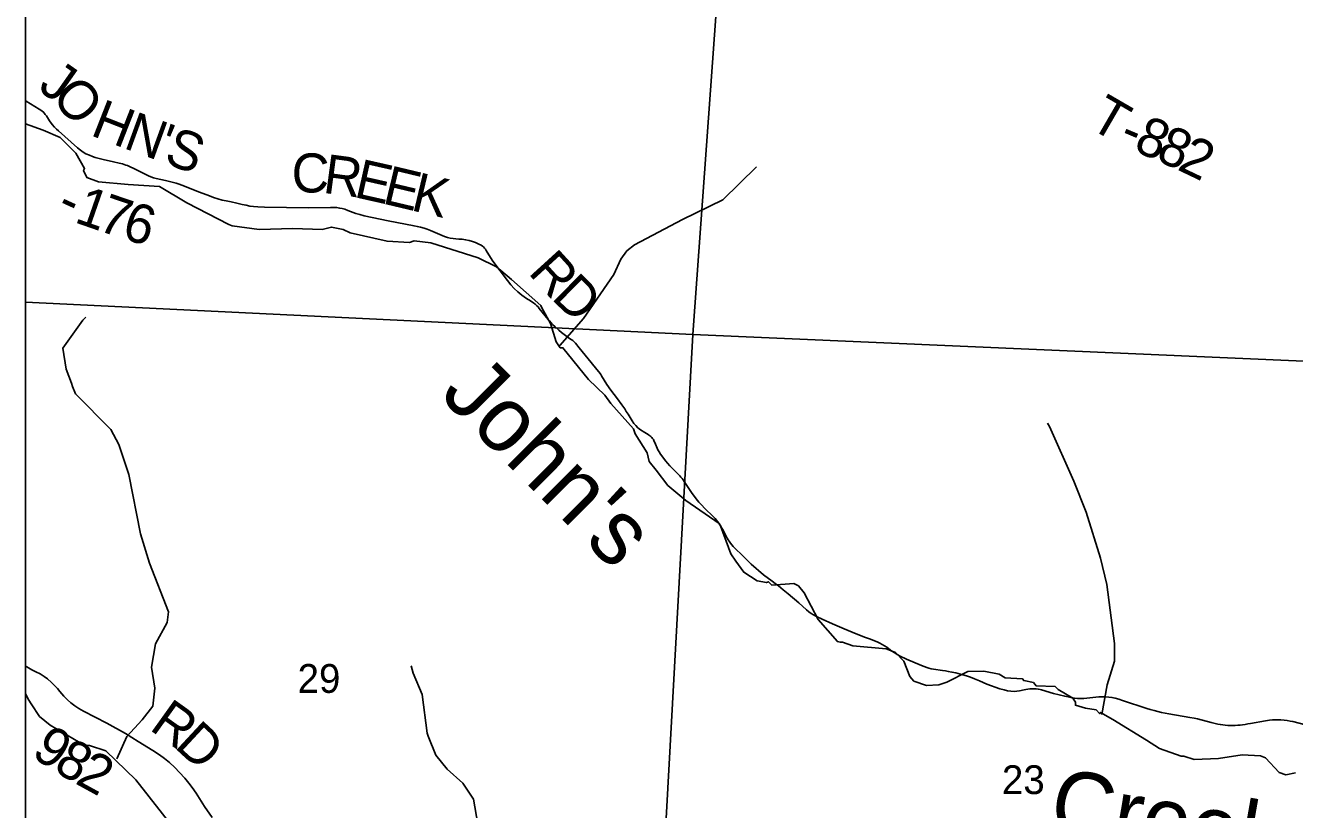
# Model space of a CAD drawing. Extents: x 0 to 34, y 0 to 22.
# Drawn here: x 2.1 to 3.946, y 17.756 to 18.895 of the extents above; entities that cross this region are included whole.
import ezdxf

# ---------------------------------------------------------------- set-up
doc = ezdxf.new("R2010")
doc.units = 0
for name, color, linetype in [('Default', 7, 'Continuous'), ('GM_X_County_Road', 7, 'Continuous'), ('GM_X_County_Road_Text', 7, 'Continuous'), ('GM_X_Minor_River', 7, 'Continuous'), ('GM_X_Minor_River_Text', 7, 'Continuous'), ('GM_X_Section', 7, 'Continuous'), ('GM_X_Section_Text', 7, 'Continuous'), ('GM_X_Township_Road', 7, 'Continuous'), ('GM_X_Township_Road_Text', 7, 'Continuous'), ('SH_Cut_Line', 7, 'Continuous')]:
    doc.layers.add(name, color=color, linetype=linetype)

msp = doc.modelspace()

# ---------------------------------------------------------------- linework, layer by layer
at = {"layer": 'Default'}
for points in [[(2.1, 19.53), (2.1, 18.4931), (3.0707, 18.4461), (3.1447, 19.4715)], [(2.1, 19.5179), (2.1, 14.1), (5.687, 14.1), (5.785, 14.1504), (5.9145, 14.1963), (5.9273, 14.1959), (5.9341, 14.3014), (6.0001, 15.328), (6.0418, 15.9539), (6.0633, 16.2368), (6.0901, 16.6706), (6.1151, 17.0743), (6.1723, 18.0255), (6.1917, 18.3385), (6.2282, 18.9116), (6.2536, 19.3066), (5.4875, 19.3459), (4.7013, 19.3856), (4.4284, 19.3984), (3.7007, 19.4348)], [(2.1, 18.4931), (2.1, 17.4608), (3.0145, 17.426), (3.0707, 18.4461)]]:
    msp.add_lwpolyline(points, close=True, dxfattribs=at)
at = {"layer": 'GM_X_County_Road'}
for points in [[(2.1, 18.7858), (2.1013, 18.785), (2.1198, 18.7738), (2.1239, 18.771), (2.1268, 18.7685), (2.129, 18.7659), (2.1305, 18.7637), (2.1352, 18.7564), (2.1389, 18.7514), (2.1422, 18.7476), (2.1453, 18.7445), (2.1481, 18.742), (2.1758, 18.7175), (2.1799, 18.7139), (2.1839, 18.711), (2.1879, 18.7089), (2.1932, 18.7065), (2.1975, 18.7047), (2.2013, 18.7034), (2.2133, 18.7005), (2.228, 18.6971), (2.2362, 18.6953), (2.2412, 18.6939), (2.2462, 18.6924), (2.2484, 18.6916), (2.2505, 18.6907), (2.2597, 18.6863), (2.279, 18.6766), (2.2825, 18.6752), (2.2864, 18.674), (2.2901, 18.673), (2.3035, 18.6698), (2.3194, 18.6658), (2.3236, 18.6646), (2.3273, 18.6632), (2.353, 18.653), (2.3678, 18.6474), (2.3734, 18.6453), (2.3797, 18.6431), (2.3863, 18.6415), (2.3921, 18.6402), (2.3994, 18.6387), (2.4073, 18.637), (2.4151, 18.6352), (2.421, 18.6339), (2.4265, 18.6328), (2.4319, 18.632), (2.4382, 18.6315), (2.4479, 18.6313), (2.5118, 18.6304), (2.5435, 18.6309), (2.5478, 18.6309), (2.5527, 18.6306), (2.5569, 18.6299), (2.5605, 18.6291), (2.5647, 18.628), (2.5688, 18.6265), (2.5726, 18.6249), (2.5764, 18.6235), (2.5807, 18.622), (2.5863, 18.6203), (2.5928, 18.6187), (2.6276, 18.6113), (2.6651, 18.604), (2.6699, 18.6031), (2.6745, 18.602), (2.6797, 18.6005), (2.6844, 18.599), (2.6891, 18.5971), (2.7093, 18.5887), (2.7139, 18.5872), (2.7177, 18.5863), (2.7219, 18.5857), (2.7258, 18.5853), (2.7304, 18.5848), (2.735, 18.5844), (2.74, 18.5837), (2.7451, 18.5826), (2.7499, 18.5812), (2.7543, 18.5796), (2.7592, 18.5775), (2.7627, 18.5757), (2.7645, 18.5746), (2.7662, 18.5733), (2.7677, 18.5717), (2.769, 18.57), (2.7701, 18.5682), (2.7714, 18.5659), (2.7795, 18.5527), (2.8008, 18.5244), (2.8058, 18.5185), (2.8106, 18.5131), (2.816, 18.5079), (2.8219, 18.5031), (2.8285, 18.4986), (2.8344, 18.495), (2.8366, 18.4937), (2.839, 18.492), (2.8412, 18.4901), (2.8433, 18.4882), (2.8455, 18.4861), (2.8473, 18.484), (2.8602, 18.4679), (2.862, 18.4657), (2.8641, 18.4633), (2.8664, 18.4608), (2.8703, 18.4571), (2.8756, 18.4523), (2.8795, 18.4489), (2.8913, 18.4405), (2.8935, 18.439), (2.8959, 18.4372), (2.8979, 18.4352), (2.8997, 18.4333), (2.9018, 18.4309), (2.9034, 18.4289), (2.9054, 18.4265), (2.9181, 18.4108), (2.9292, 18.3974), (2.9356, 18.3894), (2.9367, 18.388), (2.9379, 18.3862), (2.9455, 18.3736), (2.9513, 18.3654), (2.9611, 18.3525), (2.9673, 18.344), (2.9715, 18.3379), (2.9738, 18.3344), (2.9763, 18.3305), (2.9822, 18.3204), (2.9846, 18.3169), (2.9874, 18.3136), (2.9904, 18.3106), (2.9943, 18.3076), (2.9968, 18.306)], [(2.9968, 18.306), (2.9985, 18.305), (3.0033, 18.3022), (3.0068, 18.2999), (3.0082, 18.2988), (3.0095, 18.2978), (3.011, 18.2964), (3.0121, 18.295), (3.0131, 18.2934), (3.0139, 18.2919), (3.0145, 18.2904), (3.0152, 18.2889), (3.0198, 18.2784), (3.0214, 18.2755), (3.0234, 18.2723), (3.0311, 18.262), (3.0337, 18.2589), (3.0369, 18.2553), (3.0439, 18.2483), (3.046, 18.2463), (3.0478, 18.2445), (3.0498, 18.2426), (3.0517, 18.2406), (3.0532, 18.2388), (3.0548, 18.2368), (3.0564, 18.2348), (3.058, 18.2325), (3.0636, 18.2237), (3.0693, 18.215), (3.0772, 18.2049), (3.0793, 18.2023), (3.082, 18.1993), (3.0887, 18.1923), (3.0989, 18.1826), (3.1012, 18.1804), (3.103, 18.1784), (3.105, 18.1761), (3.1066, 18.1741), (3.1081, 18.172), (3.1094, 18.1701), (3.1106, 18.1684), (3.1117, 18.1666), (3.1128, 18.1646), (3.1139, 18.1626), (3.1183, 18.1539), (3.1204, 18.1502), (3.122, 18.1474), (3.1232, 18.1456), (3.1251, 18.143), (3.1271, 18.1404), (3.1293, 18.1378), (3.1329, 18.1342), (3.1411, 18.1264), (3.1553, 18.1124), (3.1735, 18.097), (3.186, 18.0877), (3.1904, 18.0844), (3.1951, 18.0806), (3.2017, 18.0751), (3.2089, 18.0692), (3.2245, 18.056), (3.2356, 18.0459), (3.2393, 18.0429), (3.2425, 18.0407), (3.2459, 18.0386), (3.2501, 18.0362), (3.2584, 18.0325), (3.2738, 18.0255), (3.2907, 18.0181), (3.3079, 18.011), (3.3216, 18.0059), (3.3288, 18.0033), (3.3349, 18.0009), (3.3387, 17.9993), (3.3422, 17.9976), (3.3459, 17.9955), (3.3493, 17.9935), (3.3524, 17.9915), (3.3554, 17.9892), (3.3599, 17.9859), (3.364, 17.9832), (3.3678, 17.981), (3.3722, 17.9787), (3.3811, 17.9744), (3.403, 17.9649), (3.4069, 17.9634), (3.4106, 17.9621), (3.4138, 17.9611), (3.417, 17.9603), (3.4206, 17.9596), (3.4337, 17.9576), (3.4381, 17.9571), (3.4419, 17.9565), (3.4472, 17.9555), (3.453, 17.9543), (3.4631, 17.9513), (3.4686, 17.9498), (3.4742, 17.948), (3.4802, 17.9457), (3.4874, 17.9427), (3.4982, 17.938), (3.5046, 17.9354), (3.5103, 17.9333), (3.5168, 17.9312), (3.5231, 17.9294), (3.5281, 17.9284), (3.5331, 17.9277), (3.5377, 17.9274), (3.5418, 17.9277), (3.5453, 17.9281), (3.5525, 17.9298), (3.5549, 17.9303), (3.5577, 17.9307), (3.5606, 17.931), (3.5634, 17.9312), (3.5663, 17.9312), (3.5695, 17.931), (3.5727, 17.9306), (3.5755, 17.9301), (3.5777, 17.9294), (3.5948, 17.9245), (3.6114, 17.9202), (3.6205, 17.9184), (3.6253, 17.9176), (3.63, 17.9171), (3.6348, 17.9169), (3.6389, 17.9171), (3.6611, 17.9194), (3.6656, 17.9196), (3.6705, 17.9194), (3.6753, 17.9191), (3.68, 17.9185), (3.6848, 17.9175), (3.6898, 17.9161), (3.6952, 17.9143), (3.7307, 17.9026), (3.7355, 17.9011), (3.7412, 17.8994), (3.7466, 17.8981), (3.7521, 17.8969), (3.7627, 17.8948), (3.7931, 17.8895), (3.7995, 17.8883), (3.8042, 17.8873), (3.824, 17.8822), (3.8338, 17.8799), (3.8377, 17.8792), (3.8412, 17.8787), (3.8446, 17.8783), (3.8484, 17.8779), (3.8535, 17.8776), (3.8592, 17.8779), (3.8628, 17.8781), (3.8662, 17.8784), (3.8697, 17.8789), (3.8734, 17.8794), (3.8775, 17.8801), (3.8814, 17.8808), (3.9034, 17.8847), (3.909, 17.8855), (3.9135, 17.8859), (3.9179, 17.886), (3.9222, 17.886), (3.9257, 17.8859), (3.9302, 17.8856), (3.9346, 17.8851), (3.9389, 17.8843), (3.9429, 17.8835), (3.9615, 17.8787)]]:
    msp.add_lwpolyline(points, dxfattribs=at)
at = {"layer": 'GM_X_Minor_River'}
for points in [[(2.9186, 18.3809), (2.8815, 18.4268), (2.8778, 18.4267), (2.8717, 18.4355), (2.8637, 18.4621), (2.8509, 18.4848), (2.8494, 18.4882), (2.807, 18.5258), (2.785, 18.5443), (2.7582, 18.5576), (2.6894, 18.5791), (2.6652, 18.5824), (2.6587, 18.5798), (2.6259, 18.5816), (2.5722, 18.594), (2.5623, 18.5989), (2.5449, 18.6023), (2.5313, 18.5988), (2.489, 18.6002), (2.4399, 18.5986), (2.4009, 18.6038), (2.396, 18.6061), (2.3347, 18.6375), (2.295, 18.6613), (2.2493, 18.6643), (2.2062, 18.668), (2.1892, 18.6744), (2.1846, 18.6846), (2.1861, 18.6873), (2.1732, 18.7097), (2.1505, 18.7325), (2.126, 18.743), (2.1, 18.7521)], [(2.8773, 18.43), (2.9115, 18.4692), (2.9555, 18.5332), (2.966, 18.5557), (2.9746, 18.5675), (2.9859, 18.5763), (3.0555, 18.6131), (3.1142, 18.6419), (3.1629, 18.69)], [(2.233, 17.8294), (2.2477, 17.862), (2.2696, 17.886), (2.2853, 17.9057), (2.288, 17.9318), (2.2833, 17.9627), (2.2892, 17.9963), (2.306, 18.0273), (2.308, 18.0431), (2.2807, 18.1135), (2.2672, 18.1565), (2.2506, 18.2428), (2.236, 18.2862), (2.2242, 18.3082), (2.1729, 18.36), (2.1683, 18.3704), (2.1669, 18.3753), (2.1592, 18.3957), (2.1545, 18.4262), (2.1833, 18.4671), (2.188, 18.4715)], [(3.947, 17.8092), (3.9326, 17.8061), (3.9232, 17.8095), (3.9031, 17.8308), (3.8959, 17.8338), (3.8691, 17.8349), (3.8347, 17.8298), (3.7995, 17.8282), (3.7844, 17.8331), (3.7806, 17.8331), (3.7489, 17.8444), (3.73, 17.8566), (3.6812, 17.8865), (3.6634, 17.8967), (3.6623, 17.8948), (3.657, 17.9005), (3.6415, 17.9031), (3.6267, 17.9072), (3.6271, 17.9118), (3.6229, 17.9175), (3.6017, 17.93), (3.5972, 17.9345), (3.5696, 17.9356), (3.5658, 17.9401), (3.5518, 17.9431), (3.5499, 17.9454), (3.5246, 17.9469), (3.5159, 17.9525), (3.4936, 17.9567), (3.4705, 17.9562), (3.4396, 17.9406), (3.4282, 17.9367), (3.4101, 17.9359), (3.3919, 17.942), (3.3859, 17.9492), (3.3772, 17.9712), (3.3654, 17.9841), (3.3514, 17.989), (3.3031, 17.9934), (3.2879, 17.9987), (3.2849, 17.9987), (3.2807, 17.9998), (3.2527, 18.0317), (3.2323, 18.0708), (3.224, 18.081), (3.2175, 18.084), (3.1854, 18.0817), (3.1805, 18.0866), (3.1775, 18.0854), (3.1642, 18.0881), (3.1446, 18.1006), (3.1332, 18.1165), (3.1256, 18.1275), (3.1105, 18.1681), (3.1086, 18.1715), (3.0602, 18.2049), (3.0341, 18.2268), (3.017, 18.2488), (3.0068, 18.2614), (3.0042, 18.2739), (2.9867, 18.3016), (2.9841, 18.3092), (2.9515, 18.3456), (2.9425, 18.3581), (2.9186, 18.3809)], [(3.665, 17.8938), (3.6731, 17.9368), (3.6836, 17.9714), (3.6836, 17.9968), (3.6726, 18.0826), (3.6632, 18.1209), (3.6425, 18.188), (3.6246, 18.233), (3.5892, 18.3123), (3.5863, 18.317)], [(2.7561, 17.275), (2.7409, 17.3117), (2.7415, 17.355), (2.749, 17.3916), (2.7482, 17.4151), (2.7374, 17.4436), (2.7365, 17.4535), (2.7447, 17.4847), (2.7512, 17.5369), (2.759, 17.5587), (2.7552, 17.5942), (2.7548, 17.6701), (2.7579, 17.7346), (2.7514, 17.7705), (2.7363, 17.7941), (2.7135, 17.8142), (2.6967, 17.8348), (2.6858, 17.8622), (2.6841, 17.8668), (2.6771, 17.9228), (2.664, 17.9536), (2.6609, 17.9643)], [(2.319, 17.7249), (2.2607, 17.7989), (2.2172, 17.841), (2.1933, 17.8489), (2.1854, 17.8492), (2.1362, 17.8784), (2.1207, 17.8909), (2.1086, 17.9095), (2.1052, 17.9148), (2.1, 17.9236)]]:
    msp.add_lwpolyline(points, dxfattribs=at)
at = {"layer": 'GM_X_Section'}
for points in [[(3.1447, 19.4715), (4.1716, 19.4188), (4.1036, 18.4009), (3.0707, 18.4461)], [(3.0707, 18.4461), (4.1036, 18.4009), (4.0444, 17.3771), (3.0145, 17.426)]]:
    msp.add_lwpolyline(points, close=True, dxfattribs=at)
at = {"layer": 'GM_X_Township_Road'}
msp.add_lwpolyline([(2.3714, 17.7441), (2.3606, 17.76), (2.3481, 17.7794), (2.3425, 17.7876), (2.3377, 17.7941), (2.3317, 17.8013), (2.3242, 17.8096), (2.3172, 17.8167), (2.3094, 17.8238), (2.3022, 17.8298), (2.2951, 17.835), (2.2853, 17.8415), (2.2642, 17.8547), (2.2457, 17.866), (2.2184, 17.8812), (2.1847, 17.8986), (2.1778, 17.9027), (2.1717, 17.9066), (2.1659, 17.9108), (2.161, 17.9149), (2.156, 17.9202), (2.15, 17.9271), (2.1465, 17.9314), (2.1436, 17.9347), (2.1405, 17.9379), (2.1379, 17.9405), (2.1322, 17.9454), (2.1272, 17.949), (2.1214, 17.9527), (2.1152, 17.9559), (2.1093, 17.9589), (2.1022, 17.9632), (2.1, 17.9648)], dxfattribs=at)
at = {"layer": 'SH_Cut_Line'}
msp.add_lwpolyline([(8.9, 14.1), (8.9, 20.9), (2.1, 20.9), (2.1, 14.1)], dxfattribs=at)

# ---------------------------------------------------------------- texts
at = {"layer": 'GM_X_County_Road_Text'}
for s, rotation, p in [('J', 324.8161, (2.1166, 18.8023)), ('O', 312.4504, (2.136, 18.7891)), ('H', 338.6262, (2.1929, 18.7363)), ('N', 340.0241, (2.2409, 18.7175)), ("'", 339.6384, (2.2878, 18.7005)), ('S', 339.5641, (2.2995, 18.6961)), ('C', 358.3976, (2.4863, 18.6533)), ('R', 352.3609, (2.5313, 18.6522)), ('E', 347.2922, (2.5763, 18.6462)), ('E', 346.5843, (2.6175, 18.6369)), ('K', 346.5848, (2.6589, 18.627)), ('-', 335.3927, (2.1428, 18.6217)), ('1', 340.8123, (2.1695, 18.6098)), ('7', 341.1906, (2.2029, 18.5982)), ('6', 343.3419, (2.2383, 18.5862)), ('R', 312.3317, (2.8298, 18.5356)), ('D', 315.5227, (2.8636, 18.4986))]:
    msp.add_text(s, height=0.0568, rotation=rotation, dxfattribs=at).set_placement(p)
at = {"layer": 'GM_X_Minor_River_Text'}
for s, rotation, p in [("John's", 315.0035, (2.7005, 18.3571)), ('Creek', 350.0126, (3.5857, 17.7237))]:
    msp.add_text(s, height=0.09469, rotation=rotation, dxfattribs=at).set_placement(p)
at = {"layer": 'GM_X_Section_Text'}
for s, p in [('29', (2.4958, 17.9252)), ('23', (3.5199, 17.7781))]:
    msp.add_text(s, height=0.04186, rotation=0, dxfattribs=at).set_placement(p)
at = {"layer": 'GM_X_Township_Road_Text'}
for s, rotation, p in [('T', 329.8543, (3.6443, 18.7479)), ('8', 336.7416, (3.7094, 18.714)), ('-', 337.0685, (3.688, 18.7231)), ('8', 336.3405, (3.7415, 18.7003)), ('2', 334.5195, (3.7731, 18.6864)), ('R', 324.3838, (2.2788, 17.8727)), ('D', 317.1011, (2.3153, 17.8468)), ('9', 326.5091, (2.1069, 17.8341)), ('8', 329.4437, (2.1388, 17.8131)), ('2', 331.2715, (2.1706, 17.7944))]:
    msp.add_text(s, height=0.0568, rotation=rotation, dxfattribs=at).set_placement(p)

doc.saveas('drawing.dxf')
